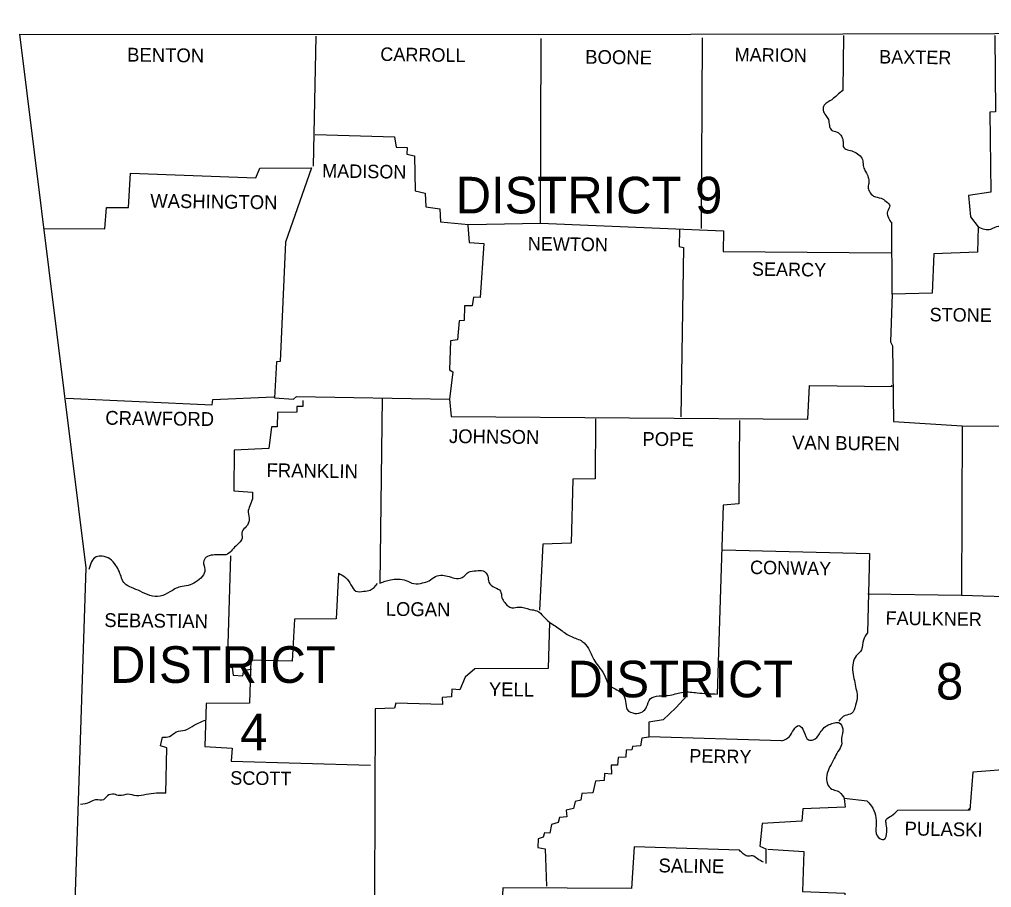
# Model space of a CAD drawing. Extents: x -17742 to 32032, y -17264 to 5867.
# Drawn here: x 1448 to 3114, y 4379 to 5867 of the extents above; entities that cross this region are included whole.
import ezdxf

# ---------------------------------------------------------------- set-up
doc = ezdxf.new("R2010")
doc.units = 0
for name, color, linetype in [('1', 7, 'Continuous'), ('2', 7, 'Continuous'), ('3', 7, 'Continuous')]:
    doc.layers.add(name, color=color, linetype=linetype)

msp = doc.modelspace()

# ---------------------------------------------------------------- linework, layer by layer
at = {"layer": '1'}
for points in [[(1448.3, 5841.4), (2338.2, 5840.9), (3119.2, 5842.5), (4040.5, 5856.8), (4467.6, 5866.7)], [(1448.3, 5841.4), (1562.2, 4926.7), (1512.7, 3433.6)], [(1956.3, 5838.1), (1951.3, 5615.2)], [(1955.2, 5669.7), (2090.6, 5665.3), (2093.9, 5647.7), (2112.6, 5647.2), (2112, 5636.1), (2125.3, 5632.8), (2126.4, 5572.9), (2143.4, 5569), (2144.5, 5545.3), (2168.7, 5542), (2169.8, 5520), (2217.7, 5515.1), (2341, 5517.8), (2342.1, 5834.3)], [(2617.8, 5835.4), (2616.2, 5508.5)], [(2860, 5839.2), (2858.9, 5745.1)], [(3119.2, 5839.2), (3120.3, 5708.2), (3110.9, 5707.7), (3112.6, 5570.7), (3074.1, 5565.2), (3077.4, 5528.3), (3090.6, 5511.2), (3089.5, 5467.7), (3014.6, 5465), (3011.9, 5397.8), (2943.6, 5395.6), (2940.3, 5314.2), (2944.2, 5307.6), (2945.8, 5177.7), (3063.6, 5170), (3062, 4880), (3155.5, 4877.2), (3155.5, 4582.2), (3081.8, 4576.7), (3076.3, 4511.8), (2952.4, 4511.2)], [(1491.8, 5508.5), (1594.7, 5507.9), (1597.5, 5544.2), (1635.4, 5544.2), (1638.7, 5603.1), (1853.4, 5595.4), (1860, 5611.9), (1948.6, 5612.5), (1904, 5484.8), (1895.2, 5280.6), (1888.6, 5280.1), (1885.3, 5218.4), (1917.8, 5215.7), (1922.7, 5220.6), (2185.2, 5215.7), (2188, 5186.5)], [(2216.6, 5514), (2218.8, 5484.3), (2244.1, 5482.6), (2237.5, 5390.1), (2226, 5390.7), (2223.8, 5375.8), (2210.6, 5375.8), (2210, 5350.5), (2201.8, 5350), (2199, 5317.5), (2186.9, 5315.8), (2185.2, 5266.3), (2190.7, 5262.5), (2185.2, 5215.7)], [(2341, 5517.8), (2654.7, 5504.6), (2654.1, 5468.8), (2942, 5466.6)], [(2943.6, 5395.6), (2943.1, 5519.5)], [(2579.3, 5506.3), (2578.7, 5477.6), (2585.9, 5476), (2581.5, 5185.4)], [(2188, 5186.5), (2798.9, 5181.6), (2801.6, 5239.3), (2943.6, 5237.7)], [(2942, 5238.2), (2943.6, 5239.9)], [(1528.1, 5217.9), (1778.5, 5206.3), (1779.6, 5215.1), (1884.2, 5220.1)], [(1933.7, 5213.5), (1933.7, 5203.6), (1923.3, 5203.6), (1923.8, 5193.7), (1890.3, 5193.1), (1889.7, 5168.3), (1880.3, 5168.3), (1875.4, 5131.5), (1816, 5128.7), (1815.4, 5058.8), (1847.3, 5056.6)], [(2069.7, 5217.9), (2065.8, 4900.3)], [(2435.1, 5182.1), (2434.6, 5079.2), (2396.6, 5078.6), (2393.3, 4969.1), (2344.8, 4967.5), (2339.3, 4854.1)], [(2681.7, 5179.4), (2680.6, 5036.3), (2654.1, 5034.1), (2643.7, 4710.5)], [(3063.6, 5170), (3346.5, 5168.3), (3370.7, 5179.9), (3369.1, 4964.7), (3352.5, 4957.6), (3337.7, 4944.9), (3332.7, 4940), (3332.2, 4878.3), (3152.2, 4878.3)], [(1809.9, 4947.7), (1804.4, 4758.3), (1812.7, 4756.1), (1814.3, 4742.9), (1830.8, 4741.8), (1832.5, 4751.2), (1845.7, 4753.4)], [(2653, 4957.6), (2904.6, 4951.5), (2901.3, 4815.6)], [(1994.8, 4917.9), (1991, 4839.2), (1919.4, 4838.7), (1915.6, 4767.1), (1844.6, 4768.8), (1842.4, 4695), (1768.1, 4694.5), (1765.9, 4620.7), (1812.7, 4618), (1811, 4595.4), (2049.9, 4588.8)], [(2901.8, 4882.2), (3062, 4880)], [(2356.4, 4833.7), (2354.2, 4754.5), (2228.7, 4753.9), (2212.2, 4739.6), (2202.9, 4717.6), (2189.1, 4718.7), (2188.5, 4706), (2172.6, 4704.4), (2173.1, 4692.8), (2093.3, 4695), (2090.6, 4686.2), (2057.6, 4685.1), (2056.5, 4363.2)], [(2592.5, 4708.3), (2572.7, 4686.8), (2551.2, 4666.4), (2526.5, 4662.6), (2526.5, 4636.7), (2514.4, 4635.1), (2512.2, 4621.8), (2498.4, 4620.7), (2497.3, 4614.7), (2487.9, 4614.1), (2487.4, 4602.6), (2474.2, 4602), (2473.1, 4588.8), (2462.1, 4588.8), (2462.6, 4573.4), (2450.5, 4574.5), (2450, 4562.4), (2435.1, 4561.3), (2430.7, 4541.5), (2412, 4539.8), (2410.3, 4528.8), (2400.4, 4526.1), (2397.7, 4514.5), (2385, 4511.8), (2386.1, 4500.2), (2373.5, 4499.1), (2371.3, 4490.3), (2359.7, 4487), (2357, 4472.1), (2348.1, 4472.7), (2345.4, 4465), (2337.1, 4462.2), (2336.6, 4447.4), (2349.2, 4445.2), (2351.5, 4381.3)], [(1699.3, 4540.9), (1700.9, 4618.5), (1689.9, 4621.8), (1693.2, 4636.7)], [(2753.8, 4630.1), (2527, 4637.3)], [(2900.7, 4527.2), (2861.1, 4531.6), (2862.7, 4516.7), (2790.6, 4514), (2788.4, 4492.5), (2720.7, 4488.7), (2716.9, 4450.1), (2726.8, 4445.2), (2726.8, 4419.9)], [(3073.5, 4512.3), (3076.3, 4515.1)], [(2681.7, 4443), (2501.7, 4448.5), (2496.7, 4377.5), (2276.6, 4378.6), (2275.5, 4354.9)], [(2730.6, 4444.6), (2792.3, 4440.8), (2790.1, 4372), (2862.2, 4369.2), (2863.3, 4309.2), (2897.4, 4306.5), (2897.4, 4296), (2929.3, 4293.8), (2930.4, 4255.3), (3003.1, 4255.3), (3005.3, 4217.3), (3072.4, 4214), (3071.9, 4142.5)]]:
    msp.add_lwpolyline(points, dxfattribs=at)
for points in [[(2858.9, 5745.1), (2849, 5736.9), (2840.2, 5729.2), (2827, 5719.8), (2825.3, 5711), (2829.7, 5702.2), (2834.1, 5695), (2835.8, 5685.1), (2839.6, 5676.9), (2849, 5673.6), (2856.7, 5666.4), (2859.4, 5656.5), (2860.5, 5647.2), (2869.3, 5642.8), (2879.2, 5639.5), (2888.6, 5632.8), (2893, 5624.6), (2894.1, 5614.1), (2898, 5605.9), (2902.4, 5596), (2903.5, 5587.7), (2902.4, 5579.5), (2904.6, 5571.8), (2911.7, 5564.1), (2924.4, 5560.2), (2933.2, 5554.7), (2939.2, 5547), (2935.4, 5537.6), (2935.9, 5529.4), (2940.9, 5519.5)], [(3090.6, 5511.2), (3112.6, 5507.4), (3125.8, 5512.3), (3135.2, 5498), (3140.1, 5487), (3148.4, 5471), (3161.6, 5466.1), (3171.5, 5457.3), (3171.5, 5447.9), (3162.7, 5439.1), (3156.1, 5430.3), (3158.3, 5419.9), (3160.5, 5405.5), (3160.5, 5391.8), (3157.2, 5379.1), (3154.4, 5367.6), (3157.2, 5357.7), (3167.6, 5359.3), (3178.6, 5367.6), (3190.2, 5367.6), (3201.2, 5361.5), (3212.8, 5351.1), (3224.3, 5353.3), (3233.7, 5356), (3246.9, 5359.9), (3256.2, 5354.9), (3264.5, 5348.3), (3274.4, 5337.9), (3283.8, 5331.3), (3295.9, 5325.2), (3310.7, 5321.3), (3324.5, 5312), (3326.7, 5296), (3326.1, 5282.3), (3325, 5265.2), (3323.9, 5246.5), (3325.6, 5228.3), (3331.6, 5216.2), (3339.3, 5201.9), (3341.5, 5188.7), (3341, 5167.8)], [(1847.3, 5056.6), (1847.3, 5045.1), (1842.9, 5033), (1840.2, 5022.5), (1841.8, 5008.7), (1836.9, 4997.7), (1829.7, 4988.9), (1829.7, 4977.9), (1821.5, 4966.4), (1812.7, 4957.6), (1804.9, 4950.4), (1791.2, 4949.3), (1779.6, 4948.8), (1768.1, 4944.9), (1763.7, 4936.6), (1765.9, 4924), (1761.5, 4911.9), (1749.9, 4902.5), (1737.3, 4896.5), (1724, 4894.3), (1705.9, 4885.5), (1689.4, 4878.3), (1671.8, 4879.4), (1655.3, 4886.6), (1640.4, 4893.2), (1628.8, 4899.8), (1619.5, 4920.1), (1613.4, 4931.1), (1603, 4942.2), (1590.3, 4946.6), (1579.9, 4945.5), (1567.2, 4924)], [(1994.8, 4917.9), (2006.9, 4910.2), (2016.3, 4897.6), (2024.5, 4887.1), (2038.3, 4886.6), (2049.3, 4888.8), (2062, 4899.8)], [(2065.8, 4900.3), (2084, 4906.4), (2097.2, 4907.5), (2110.4, 4905.3), (2124.2, 4899.8), (2139, 4900.9), (2150, 4904.7), (2161, 4911.9), (2173.1, 4914.1), (2184.7, 4911.9), (2196.8, 4908.6), (2210, 4912.4), (2217.7, 4919.6), (2230.9, 4921.8), (2242.5, 4921.8), (2250.7, 4912.4), (2252.4, 4902.5), (2262.8, 4893.2), (2272.2, 4887.1), (2275, 4875.6), (2279.9, 4867.3), (2284.9, 4861.8), (2292, 4858.5), (2304.1, 4859.6), (2322.8, 4855.7), (2334.9, 4853), (2345.9, 4843.6), (2356.4, 4833.7)], [(2356.4, 4833.7), (2375.7, 4820.5), (2393.8, 4809), (2412.5, 4800.7), (2423, 4788.6), (2432.4, 4769.9), (2440.1, 4758.3), (2450, 4744), (2457.1, 4728.1), (2468.7, 4719.3), (2480.8, 4711.6), (2486.8, 4697.8), (2489.6, 4684), (2502.8, 4677.4), (2515.5, 4680.2), (2522.6, 4688.4), (2529.2, 4702.7), (2544.1, 4707.2), (2563.3, 4708.8), (2585.4, 4713.8), (2609.6, 4712.7), (2643.7, 4710.5)], [(2901.3, 4815.6), (2894.1, 4802.9), (2890.8, 4786.4), (2882, 4775.9), (2876.5, 4763.8), (2875.9, 4747.9), (2878.7, 4733.6), (2881.4, 4719.8), (2883.6, 4707.2), (2880.9, 4691.2), (2873.7, 4677.4), (2862.7, 4673.6), (2852.3, 4664.2)], [(1693.2, 4636.7), (1705.3, 4637.8), (1716.9, 4645.5), (1732.3, 4648.8), (1747.7, 4657.1), (1767, 4665.9)], [(2753.8, 4630.1), (2767.5, 4637.8), (2774.7, 4649.4), (2783.5, 4656.5), (2792.3, 4646.6), (2800, 4632.3), (2808.2, 4632.3), (2818.7, 4642.2), (2825.3, 4651), (2833.6, 4657.6), (2842.4, 4660.4), (2851.7, 4661.5), (2858.9, 4651), (2856.7, 4634.5), (2856.7, 4623.5), (2850.6, 4611.9), (2844, 4599.8), (2836.9, 4586.1), (2831.4, 4571.2), (2832.5, 4556.9), (2840.2, 4547.5), (2849, 4544.8), (2861.1, 4532.7)], [(1699.3, 4540.9), (1683.3, 4540.4), (1665.2, 4538.2), (1648.6, 4536), (1633.8, 4538.7), (1620, 4536.5), (1610.7, 4538.7), (1599.1, 4536), (1592.5, 4529.4), (1578.8, 4529.4), (1568.8, 4525), (1552.9, 4521.1)], [(2900.7, 4527.2), (2910.1, 4515.1), (2915.6, 4498.6), (2915.6, 4479.9), (2920, 4464.4), (2928.8, 4461.1), (2934.3, 4474.4), (2933.2, 4487.6), (2933.2, 4495.3), (2942.5, 4501.9), (2952.4, 4511.2)], [(2722.9, 4422.6), (2712.5, 4428.1), (2704.2, 4433.1), (2695.4, 4432.5), (2688.3, 4436.9), (2681.7, 4443)]]:
    msp.add_spline(points, degree=3, dxfattribs=at)

# ---------------------------------------------------------------- texts
at = {"layer": '2'}
for s, height, rotation, p in [('BENTON', 23.67, 359.2527, (1632.7, 5794.6)), ('CARROLL', 23.11, 359.1481, (2066.4, 5795.8)), ('BOONE', 23.67, 359.4001, (2417.5, 5790.8)), ('MARION', 23.11, 359.1854, (2673.4, 5795.2)), ('BAXTER', 23.11, 359.2559, (2921.1, 5791.3)), ('MADISON', 23.11, 359.0906, (1966.8, 5596)), ('WASHINGTON', 23.66, 359.232, (1672.3, 5544.2)), ('NEWTON', 23.11, 359.2717, (2319, 5471)), ('SEARCY', 23.11, 359.2527, (2703.1, 5427.6)), ('STONE', 23.11, 359.4001, (3007.5, 5349.4)), ('CRAWFORD', 23.66, 359.2771, (1595.3, 5172.2)), ('JOHNSON', 23.67, 359.3514, (2184.1, 5140.8)), ('POPE', 23.67, 359.6155, (2515.5, 5135.9)), ('VAN BUREN', 23.67, 359.3508, (2771.9, 5129.8)), ('FRANKLIN', 23.67, 359.1815, (1871.5, 5082.5)), ('CONWAY', 23.11, 359.0371, (2699.8, 4916.3)), ('LOGAN', 23.67, 359.3969, (2075.7, 4844.7)), ('SEBASTIAN', 23.66, 359.2816, (1593.6, 4825.5)), ('FAULKNER', 23.11, 359.2486, (2932.1, 4829.3)), ('YELL', 23.67, 359.1987, (2252.4, 4707.2)), ('PERRY', 23.11, 359.0858, (2595.8, 4593.2)), ('SCOTT', 23.11, 359.4063, (1809.4, 4555.3)), ('PULASKI', 23.67, 359.053, (2964.5, 4468.3)), ('SALINE', 23.67, 359.1491, (2543, 4405))]:
    msp.add_text(s, height=height, rotation=rotation, dxfattribs=at).set_placement(p)
at = {"layer": '3'}
for s, height, p in [('DISTRICT 9', 62.74, (2195.7, 5534.3)), ('DISTRICT', 62.74, (1603.5, 4729.7)), ('DISTRICT', 62.74, (2387.2, 4704.9)), ('8', 62.7, (3018.5, 4701.1)), ('4', 62.7, (1826.4, 4614.1))]:
    msp.add_text(s, height=height, dxfattribs=at).set_placement(p)

doc.saveas('drawing.dxf')
